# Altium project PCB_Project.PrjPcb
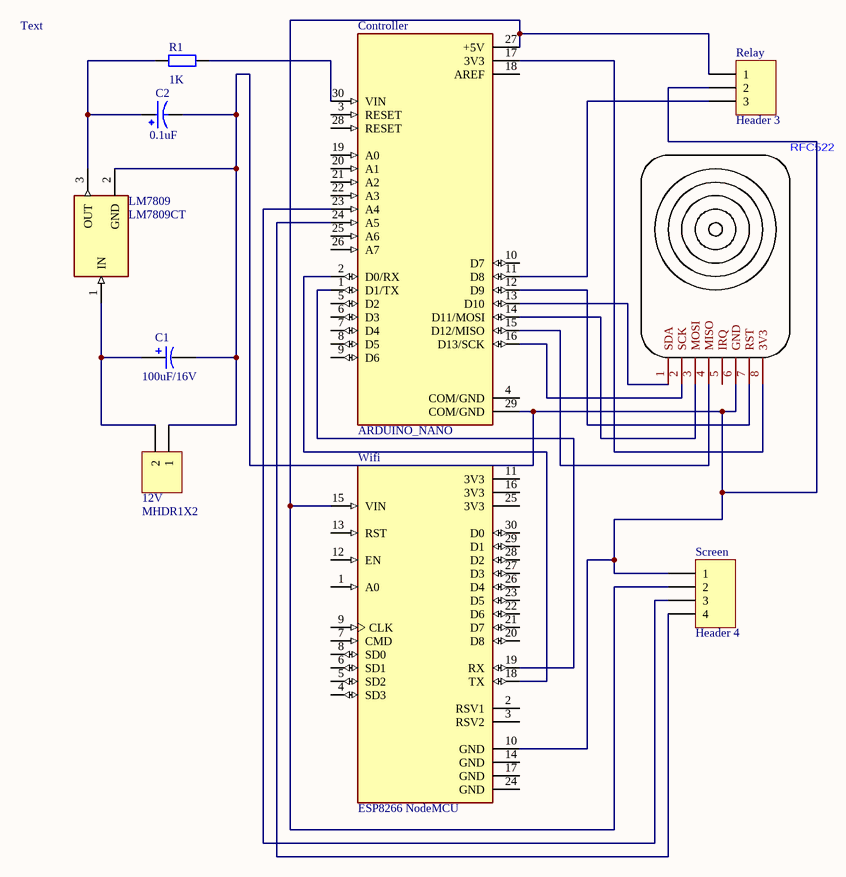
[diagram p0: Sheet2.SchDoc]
1 sheet, 10 parts. Net scope: global (net labels, ports and power ports of the same name join across sheets).
Board file: PCB1.PcbDoc

## Sheet Sheet2.SchDoc
size A4; SheetNumber: 1; SheetTotal: 1

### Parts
12V  MHDR1X2  [MHDR1X2]
C1  100uF/16V  [CAP_ALUM_SMD_6354_TYPE_D]
C2  0.1uF  [CAPPRD200W50D500H1100]
Controller  ARDUINO_NANO  [SHIELD_ARDUINO_NANO]
LM7809  LM7809CT  [TO254P470X1016X1879-3P]
R1  value 1K  [AXIAL-0.4]
Relay  Header 3  [HDR1X3]
RFC522  (no value)  [MFRC522_FURO]
Screen  Header 4  [HDR1X4]
Wifi  ESP8266 NodeMCU  [MODULE_ZC563900]

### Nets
Net12V_1: 12V.1 C1.2 C2.N Controller.29(COM/GND) LM7809.2(GND) Relay.2 RFC522.6(GND) Screen.1 Wifi.10(GND)
Net12V_2: 12V.2 C1.1 LM7809.1(IN)
NetC2_P: C2.P LM7809.3(OUT) R1.1
NetController_1: Controller.1(D1/TX) Wifi.19(RX)
NetController_2: Controller.2(D0/RX) Wifi.18(TX)
NetController_11: Controller.11(D8) Relay.3
NetController_12: Controller.12(D9) RFC522.7(RST)
NetController_13: Controller.13(D10) RFC522.1(SDA)
NetController_14: Controller.14(D11/MOSI) RFC522.3(MOSI)
NetController_15: Controller.15(D12/MISO) RFC522.4(MISO)
NetController_16: Controller.16(D13/SCK) RFC522.2(SCK)
NetController_17: Controller.17(3V3) RFC522.8(3V3)
NetController_23: Controller.23(A4) Screen.3
NetController_24: Controller.24(A5) Screen.4
NetController_27: Controller.27(+5V) Relay.1 Screen.2 Wifi.15(VIN)
NetController_30: Controller.30(VIN) R1.2

Not connected (* = marked no-connect by the designer): Controller 3(RESET) 4(COM/GND) 5(D2) 6(D3) 7(D4) 8(D5) 9(D6) 10(D7) 18(AREF) 19(A0) 20(A1) 21(A2) 22(A3) 25(A6) 26(A7) 28(RESET); RFC522 5(IRQ); Wifi 1(A0) 2(RSV1) 3(RSV2) 4(SD3) 5(SD2) 6(SD1) 7(CMD) 8(SD0) 9(CLK) 11(3V3) 12(EN) 13(RST) 14(GND) 16(3V3) 17(GND) 20(D8) 21(D7) 22(D6) 23(D5) 24(GND) 25(3V3) 26(D4) 27(D3) 28(D2) 29(D1) 30(D0)

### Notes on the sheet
- Text

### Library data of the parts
12V = MHDR1X2: Header, 2-Pin
C1 = EEE-FK1C101P: CAP ALUM 100uF 20% 16V SMD; MFR: Panasonic; Solder: SMT
C2 = EEUEB1J1R0S: CAP ALUM 1UF 20% 63V RADIAL; MF: Panasonic
Controller = ARDUINO_NANO: Small, complete, and breadboard-friendly board based on the ATmega328 (Arduino Nano 3.x)
LM7809 = LM7809CT: Linear Voltage Regulator IC 1 Output 1A TO-220-3; MF: Fujitsu
R1 = Res2: Resistor
Relay = Header 3: Header, 3-Pin
RFC522 = MFRC522_SYM
Screen = Header 4: Header, 4-Pin
Wifi = ZC563900: NodeMcu Lua ESP8266 WIFI Internet of Things Network Development Module Board; MF: YKS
